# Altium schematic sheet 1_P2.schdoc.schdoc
size 309 x 223 mm; Symbol: A4_Schematic_0605; Device: A4_Schematic_0605; @Project Name: MDIO-Board_Rev_01(0124); @Page Count: 10; @Update Date: 2024-05-25; @Create Date: 2024-05-19; @Schematic Name: Schematic1; @Page No: 2; @Page Name: P2
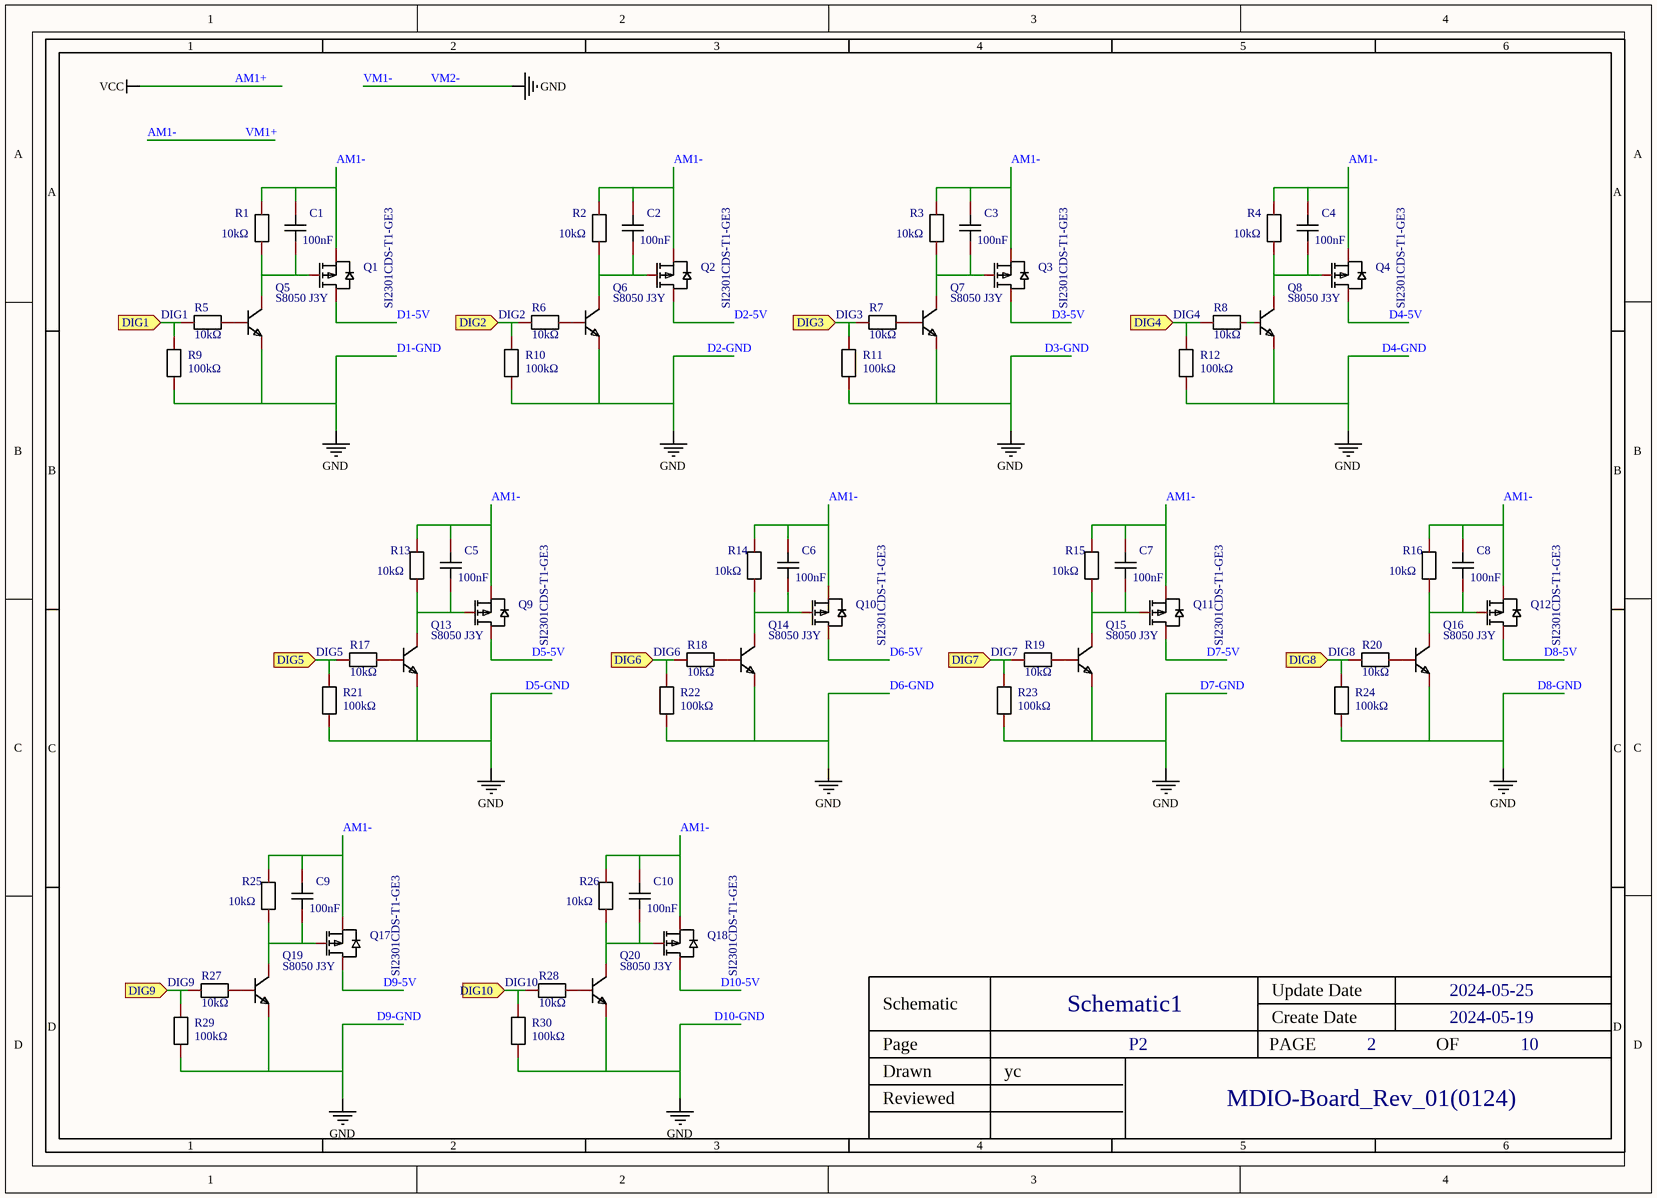
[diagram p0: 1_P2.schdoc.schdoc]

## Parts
C1  100nF  [C0603]
C2  100nF  [C0603]
C3  100nF  [C0603]
C4  100nF  [C0603]
C5  100nF  [C0603]
C6  100nF  [C0603]
C7  100nF  [C0603]
C8  100nF  [C0603]
C9  100nF  [C0603]
C10  100nF  [C0603]
Q1  SI2301CDS-T1-GE3  [SOT-23-3_L3.0-W1.7-P0.95-LS2.9-BR]
Q2  SI2301CDS-T1-GE3  [SOT-23-3_L3.0-W1.7-P0.95-LS2.9-BR]
Q3  SI2301CDS-T1-GE3  [SOT-23-3_L3.0-W1.7-P0.95-LS2.9-BR]
Q4  SI2301CDS-T1-GE3  [SOT-23-3_L3.0-W1.7-P0.95-LS2.9-BR]
Q5  S8050 J3Y  [SOT-23-3_L3.0-W1.7-P0.95-LS2.9-BR]
Q6  S8050 J3Y  [SOT-23-3_L3.0-W1.7-P0.95-LS2.9-BR]
Q7  S8050 J3Y  [SOT-23-3_L3.0-W1.7-P0.95-LS2.9-BR]
Q8  S8050 J3Y  [SOT-23-3_L3.0-W1.7-P0.95-LS2.9-BR]
Q9  SI2301CDS-T1-GE3  [SOT-23-3_L3.0-W1.7-P0.95-LS2.9-BR]
Q10  SI2301CDS-T1-GE3  [SOT-23-3_L3.0-W1.7-P0.95-LS2.9-BR]
Q11  SI2301CDS-T1-GE3  [SOT-23-3_L3.0-W1.7-P0.95-LS2.9-BR]
Q12  SI2301CDS-T1-GE3  [SOT-23-3_L3.0-W1.7-P0.95-LS2.9-BR]
Q13  S8050 J3Y  [SOT-23-3_L3.0-W1.7-P0.95-LS2.9-BR]
Q14  S8050 J3Y  [SOT-23-3_L3.0-W1.7-P0.95-LS2.9-BR]
Q15  S8050 J3Y  [SOT-23-3_L3.0-W1.7-P0.95-LS2.9-BR]
Q16  S8050 J3Y  [SOT-23-3_L3.0-W1.7-P0.95-LS2.9-BR]
Q17  SI2301CDS-T1-GE3  [SOT-23-3_L3.0-W1.7-P0.95-LS2.9-BR]
Q18  SI2301CDS-T1-GE3  [SOT-23-3_L3.0-W1.7-P0.95-LS2.9-BR]
Q19  S8050 J3Y  [SOT-23-3_L3.0-W1.7-P0.95-LS2.9-BR]
Q20  S8050 J3Y  [SOT-23-3_L3.0-W1.7-P0.95-LS2.9-BR]
R1  10kΩ  [R0603]
R2  10kΩ  [R0603]
R3  10kΩ  [R0603]
R4  10kΩ  [R0603]
R5  10kΩ  [R0603]
R6  10kΩ  [R0603]
R7  10kΩ  [R0603]
R8  10kΩ  [R0603]
R9  100kΩ  [R0603]
R10  100kΩ  [R0603]
R11  100kΩ  [R0603]
R12  100kΩ  [R0603]
R13  10kΩ  [R0603]
R14  10kΩ  [R0603]
R15  10kΩ  [R0603]
R16  10kΩ  [R0603]
R17  10kΩ  [R0603]
R18  10kΩ  [R0603]
R19  10kΩ  [R0603]
R20  10kΩ  [R0603]
R21  100kΩ  [R0603]
R22  100kΩ  [R0603]
R23  100kΩ  [R0603]
R24  100kΩ  [R0603]
R25  10kΩ  [R0603]
R26  10kΩ  [R0603]
R27  10kΩ  [R0603]
R28  10kΩ  [R0603]
R29  100kΩ  [R0603]
R30  100kΩ  [R0603]

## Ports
DIG1 (in), DIG2 (in), DIG3 (in), DIG4 (in), DIG5 (in), DIG6 (in), DIG7 (in), DIG8 (in), DIG9 (in), DIG10 (in)

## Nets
D1-GND: Q5.2(E) Q6.2(E) Q7.2(E) Q8.2(E) Q13.2(E) Q14.2(E) Q15.2(E) Q16.2(E) Q19.2(E) Q20.2(E) R9.1 R10.1 R11.1 R12.1 R21.1 R22.1 R23.1 R24.1 R29.1 R30.1  [also labelled D10-GND, D2-GND, D3-GND, D4-GND, D5-GND, D6-GND, D7-GND, D8-GND, D9-GND, GND, VM1-, VM2-]
AM1-: C1.1 C2.1 C3.1 C4.1 C5.1 C6.1 C7.1 C8.1 C9.1 C10.1 Q1.2(S) Q2.2(S) Q3.2(S) Q4.2(S) Q9.2(S) Q10.2(S) Q11.2(S) Q12.2(S) Q17.2(S) Q18.2(S) R1.2 R2.2 R3.2 R4.2 R13.2 R14.2 R15.2 R16.2 R25.2 R26.2  [also labelled VM1+]
D1-5V: Q1.3(D)
D2-5V: Q2.3(D)
D3-5V: Q3.3(D)
D4-5V: Q4.3(D)
D5-5V: Q9.3(D)
D6-5V: Q10.3(D)
D7-5V: Q11.3(D)
D8-5V: Q12.3(D)
D9-5V: Q17.3(D)
D10-5V: Q18.3(D)
DIG1: R5.2 R9.2 ; port DIG1
DIG2: R6.2 R10.2 ; port DIG2
DIG3: R7.2 R11.2 ; port DIG3
DIG4: R8.2 R12.2 ; port DIG4
DIG5: R17.2 R21.2 ; port DIG5
DIG6: R18.2 R22.2 ; port DIG6
DIG7: R19.2 R23.2 ; port DIG7
DIG8: R20.2 R24.2 ; port DIG8
DIG9: R27.2 R29.2 ; port DIG9
DIG10: R28.2 R30.2 ; port DIG10
NetC1_2: C1.2 Q1.1(G) Q5.3(C) R1.1
NetC2_2: C2.2 Q2.1(G) Q6.3(C) R2.1
NetC3_2: C3.2 Q3.1(G) Q7.3(C) R3.1
NetC4_2: C4.2 Q4.1(G) Q8.3(C) R4.1
NetC5_2: C5.2 Q9.1(G) Q13.3(C) R13.1
NetC6_2: C6.2 Q10.1(G) Q14.3(C) R14.1
NetC7_2: C7.2 Q11.1(G) Q15.3(C) R15.1
NetC8_2: C8.2 Q12.1(G) Q16.3(C) R16.1
NetC9_2: C9.2 Q17.1(G) Q19.3(C) R25.1
NetC10_2: C10.2 Q18.1(G) Q20.3(C) R26.1
NetQ5_1: Q5.1(B) R5.1
NetQ6_1: Q6.1(B) R6.1
NetQ7_1: Q7.1(B) R7.1
NetQ8_1: Q8.1(B) R8.1
NetQ13_1: Q13.1(B) R17.1
NetQ14_1: Q14.1(B) R18.1
NetQ15_1: Q15.1(B) R19.1
NetQ16_1: Q16.1(B) R20.1
NetQ19_1: Q19.1(B) R27.1
NetQ20_1: Q20.1(B) R28.1

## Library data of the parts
C1-C10 = CC0603KRX7R9BB104: Manufacturer: YAGEO(国巨); Add into BOM: yes; Tolerance: ±10%; Description: Capacitance: Tolerance:±10% Tolerance:±10% Voltage Rated: Temperature Coefficient:
Q1-Q4 Q9-Q12 Q17 Q18 = SI2301CDS-T1-GE3: Manufacturer: VISHAY(威世); Add into BOM: yes; Type: 1个PChannel; Power Dissipation (Pd): ；; Drain Source On Resistance (RDS(on)@Vgs,Id): 112mΩ@4.5V,2.8A; Gate Threshold Voltage (Vgs(th)@Id): 1V@250uA; Total Gate Charge (Qg@Vgs): 10nC@4.5V; Input Capacitance (Ciss@Vds): 405pF@10V; Description: Type:1个PChannel Drain Source Voltage (Vdss): Continuous Drain Current (Id): Power Dissipation (Pd):； Drain Source On Resistance (RDS(on)@Vgs,Id):112mΩ@4.5V,2.8A Gate Threshold Voltage (Vgs(th)@Id):1V@250uA Total Gate Charge (Qg@Vgs):10nC@4.5V Input Capaci
Q5-Q8 Q13-Q16 Q19 Q20 = S8050 J3Y_C2146: Manufacturer: CJ(江苏长电/长晶); Symbol: S8050_C2146; Add into BOM: yes; DC Current Gain (hFE@Ic,Vce): 200@50mA,1V; Transition Frequency (fT): 150MHz; Collector Cut-Off Current (Icbo): 100nA; Collector-Emitter Saturation Voltage (VCE(sat)@Ic,Ib): 600mV@500mA,50mA; Description: Transistor Type: Collector Current (Ic): Collector-Emitter Breakdown Voltage (Vceo): Power Dissipation (Pd): DC Current Gain (hFE@Ic,Vce):200@50mA,1V DC Current Gain (hFE@Ic,Vce):200@50mA,1V Transition Frequency (fT):150MHz Collector Cut-Off Current (Icbo
R1-R8 R13-R20 R25-R28 = SCR0603J10K: Manufacturer: VO(翔胜); Add into BOM: yes; Tolerance: ±5%; Description: Type:Thick Film Resistors Resistance: Tolerance:±5% Tolerance:±5% Power(Watts): Overload Voltage (Max): Operating Temperature Range:-55℃~+155℃ Operating Temperature Range:-55℃~+155℃
R9-R12 R21-R24 R29 R30 = SCR0603F100K: Manufacturer: VO(翔胜); Add into BOM: yes; Tolerance: ±1%; Description: Type:Thick Film Resistors Resistance: Tolerance:±1% Tolerance:±1% Power(Watts): Overload Voltage (Max): Operating Temperature Range:-55℃~+155℃ Operating Temperature Range:-55℃~+155℃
